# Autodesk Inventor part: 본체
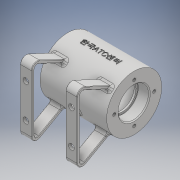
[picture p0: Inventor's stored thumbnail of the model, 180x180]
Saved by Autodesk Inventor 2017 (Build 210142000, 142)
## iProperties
Part Number: 본체
Material: 일반
Document SubType Name: Modeling
Designer: Administrator
Density: 1 g/cm^3
Appearance: 기본값
Author: Administrator
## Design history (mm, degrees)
sketch "스케치1"
  geometry: L1 (0, 0)-(70, 0); L2 (0, 29)-(70, 29); L3 (70, 29)-(70, 16); L4 (70, 16)-(58, 16); L5 (58, 16)-(58, 14); L6 (58, 14)-(56, 14); L7 (56, 14)-(56, 21); L8 (56, 21)-(14, 21); L9 (14, 21)-(14, 14); L10 (14, 14)-(12, 14); L11 (12, 14)-(12, 16); L12 (12, 16)-(0, 16); L13 (0, 16)-(0, 29)
  constraints: 26 end point, 10 perpendicular, 2 horizontal, 2 point on line, 2 vertical alignment
  dimensions: "d0" = 70 distance of L1.start L1.end; "d1" = 58 diameter of L2 L1; "d2" = 42 diameter of L8 L1; "d3" = 28 diameter of L10 L1; "d4" = 32 diameter of L4 L1; "d5" = 32 diameter of L12 L1; "d6" = 12 distance of L11.end L12.end; "d7" = 42 distance of L7.end L8.end; "d8" = 12 distance of L3.end L4.end; "d9" = 2 distance of L5.end L6.end
revolve "회전1" sketch "스케치1" stored, may be unused: angle "d10" = 90 deg
node "작업 평면1"
sketch "스케치2"
  geometry: L1 (0, 29)-(0, -29) reference; C1 r 5 at (-35, 0); 1 further point
  constraints: 1 centre point, 1 horizontal alignment
  dimensions: "d12" = 10 diameter of C1; "d13" = 35 distance from line of C1.centre L1
extrude "돌출1" join sketch "스케치2" stored distance "d14" = 10; taper "d15" = 0 deg
node "작업 평면2"
sketch "스케치4"
  geometry: L1 (0, 0)-(34.074, 0); L2 (0, 0)-(30.07, -10.945); L3 (0, 0)-(32, 0)
  constraints: 6 end point, 2 horizontal, 1 equal length
  dimensions: "d18" = 32 distance of L1.start L2.end; "d19" = 20 deg angle of L2 L3; "d43" = 34.07448 distance of L1.start L1.end
node "작업 평면3"
sketch "스케치5"
  geometry: C1 r 6 at (0, 0); 4 further points
  constraints: 1 centre point, 1 coincident
  dimensions: "d20" = 12 diameter of C1
extrude "돌출2" join sketch "스케치5" stored distance "d21" = 10; taper "d22" = 0 deg
node "작업 평면5"
sketch "스케치8"
  geometry: L1 (20.15, -20.856)-(46.064, -35.399); L2 (55, -30.167)-(55, 30.167); L3 (46.464, 35.605)-(18.32, 22.481); L4 (20.72, 20.29)-(47.732, 32.886); L5 (52, 30.167)-(52, -30.167); L6 (47.532, -32.783)-(22.253, -18.596); A1 r 29 centre (0, 0) between (20.15, -20.856) and (18.32, 22.481) reference; A2 r 29 centre (0, 0) between (20.15, -20.856) and (18.32, 22.481) reference; A3 r 6 centre (49, 30.167) between (55, 30.167) and (46.464, 35.605); A4 r 6 centre (49, -30.167) between (46.064, -35.399) and (55, -30.167); A5 r 3 centre (49, 30.167) between (52, 30.167) and (47.732, 32.886); A6 r 3 centre (49, -30.167) between (47.532, -32.783) and (52, -30.167); 4 further points
  constraints: 14 point on circle, 12 end point, 4 centre point, 4 point on line, 4 tangent, 1 equal radius, 1 horizontal alignment, 1 midpoint, 1 vertical, 2 other
  dimensions: "d32" = 80 distance of point (55, -40.415) point (55, 39.585); "d33" = 55 distance from line of L2 A1.centre; "d35" = 65 deg angle of L2 L3; "d36" = 6 radius of A3; "d37" = 3 distance between parallel lines of L3 L4; "d38" = 60.6979 deg angle of L1 L2; "d39" = 3 distance between parallel lines of L6 L1; "d40" = 3 distance between parallel lines of L2 L5
extrude "돌출3" join sketch "스케치8" distance "d41" = 12; taper "d42" = 0 deg
sketch "스케치9"
  geometry: L1 (0, 60.334)-(0, 0) reference; C1 r 3 at (6, 48.167); C2 r 3 at (6, 12.167); 1 further point
  constraints: 2 centre point, 1 vertical alignment
  dimensions: "d44" = 6 diameter of C1; "d45" = 6 diameter of C2; "d46" = 36 distance of C2.centre C1.centre; "d47" = 6 distance from line of C1.centre L1; "d48" = 18 vertical distance of point (-5, 30.167) C1.centre
extrude "돌출4" cut sketch "스케치9" distance "d49" = 12; taper "d50" = 0 deg
node "작업 평면6"
sketch "스케치10"
  geometry: 3 further points
  constraints: 2 horizontal alignment, 1 other
hole "구멍1" sketch "스케치10" at (21, 0) diameter "d52" = 3.242; stored, may be unused: countersink angle "d56" = 90 deg, drill point angle "d58" = 118 deg; dims "d53" = 8, "d54" = 4, "d55" = 2, "d57" = 10
hole "구멍2" diameter "d64" = 3; stored, may be unused: countersink angle "d68" = 90 deg, drill point angle "d70" = 118 deg; dims "d62" = 10, "d63" = 10, "d65" = 6, "d66" = 4, "d67" = 2, "d69" = 30
hole "구멍3" diameter "d73" = 5.188; stored, may be unused: countersink angle "d77" = 90 deg, drill point angle "d79" = 118 deg; dims "d71" = 10, "d72" = 10, "d74" = 6, "d75" = 4, "d76" = 2, "d78" = 8
fillet "모깎기1" dims "d80" = 3
fillet "모깎기2" dims "d81" = 0.3
chamfer "모따기1" distance "d82" = 1; stored, may be unused: second distance "d83" = 2, angle "d84" = 45 deg
fillet "모깎기3" dims "d85" = 1
fillet "모깎기4" dims "d89" = 0.5
fillet "모깎기5" dims "d90" = 3
hole "구멍4" diameter "d93" = 5.188; stored, may be unused: countersink angle "d97" = 90 deg, drill point angle "d99" = 118 deg; dims "d91" = 10, "d92" = 10, "d94" = 12, "d95" = 4, "d96" = 2, "d98" = 16
node "작업 평면7"
sketch "스케치11"
  geometry: L1 (0, -29)-(0, 29) reference; L2 (0, 29)-(70, 29) reference; 2 further points
  constraints: 1 other
  dimensions: "d101" = 35 distance from line of point (35, 0) L1; "d102" = 29 distance from line of point (35, 0) L2
feature "엠보싱1" sketch "스케치11" dims "d0" = 70, "d1" = 58, "d2" = 42, "d3" = 28, "d4" = 32, "d5" = 32, "d6" = 12, "d7" = 42, "d8" = 12, "d9" = 2, "d103" = 0.5, "d104" = 0
node "솔리드1"
mirror "미러1"
pattern_circular "원형 패턴1" dims angle "d60" = 360 deg
mirror "미러2"
other parameters: "d11" = 32, "d16" = 35, "d31" = 5, "d100" = 90.25
